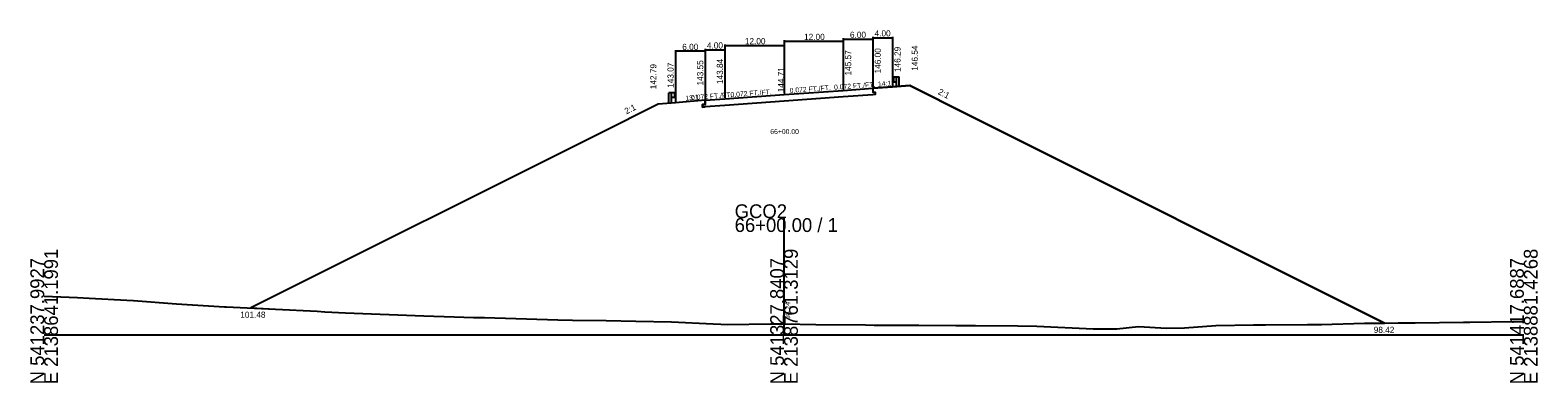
# Model space of a CAD drawing. Extents: x -14327 to 8886, y -10 to 39048.
# Drawn here: x 1997.2 to 2302.8, y 31990.3 to 32061.8 of the extents above; entities that cross this region are included whole.
import ezdxf

# ---------------------------------------------------------------- set-up
doc = ezdxf.new("R2010")
doc.units = 0
for name, color, linetype in [('Level 1', 7, 'Continuous'), ('Level 5', 7, 'Continuous'), ('Level 53', 7, 'Continuous'), ('Level 54', 7, 'Continuous'), ('Level 55', 7, 'Continuous'), ('Level 7', 7, 'Continuous'), ('RD_GPK_XS_Cell', 7, 'Continuous'), ('RD_XS_EwShp', 7, 'Continuous'), ('RD_XS_ExGround', 7, 'Continuous'), ('RD_XS_Pave', 7, 'Continuous'), ('RD_XS_TX_Elev_EX', 7, 'Continuous'), ('RD_XS_TX_Elev_PR', 7, 'Continuous'), ('RD_XS_TX_Station', 7, 'Continuous')]:
    doc.layers.add(name, color=color, linetype=linetype)

msp = doc.modelspace()

# ---------------------------------------------------------------- linework, layer by layer
at = {"layer": 'Level 1'}
for p, q in [((2172.02, 32052.11), (2172.14, 32052.2)), ((2172.02, 32052.01), (2172.14, 32051.91)), ((2172.02, 32051.58), (2172.14, 32051.67)), ((2172.02, 32051.48), (2172.14, 32051.39)), ((2172.15, 32052.2), (2172.23, 32052.22)), ((2172.15, 32051.38), (2172.23, 32051.37)), ((2172.16, 32051.87), (2172.16, 32051.72)), ((2172.23, 32052.28), (2172.23, 32051.31)), ((2172.23, 32052.28), (2172.78, 32052.28)), ((2172.23, 32051.31), (2172.78, 32051.31)), ((2172.78, 32050.29), (2172.78, 32052.28)), ((2172.78, 32052.28), (2173.34, 32052.28)), ((2173.34, 32050.29), (2173.34, 32052.28)), ((2126.66, 32047.07), (2126.66, 32049.06)), ((2127.22, 32049.06), (2126.66, 32049.06)), ((2127.22, 32047.07), (2127.22, 32049.06)), ((2127.77, 32049.06), (2127.22, 32049.06)), ((2127.77, 32048.09), (2127.22, 32048.09)), ((2127.77, 32049.06), (2127.77, 32048.09)), ((2127.85, 32048.99), (2127.77, 32049)), ((2127.85, 32048.16), (2127.77, 32048.15)), ((2127.84, 32048.65), (2127.84, 32048.5)), ((2127.98, 32048.89), (2127.86, 32048.98)), ((2127.98, 32048.79), (2127.86, 32048.7)), ((2127.98, 32048.36), (2127.86, 32048.45)), ((2127.98, 32048.26), (2127.86, 32048.17))]:
    msp.add_line(p, q, dxfattribs=at)
for centre, radius, start, end in [((2172.07, 32052.06), 0.0651, 129.0336, 230.9663), ((2172.07, 32051.53), 0.0651, 129.0336, 230.9663), ((2172.09, 32051.72), 0.0651, 302.9895, 0), ((2172.15, 32052.18), 0.026, 90, 129.0505), ((2172.09, 32051.87), 0.0651, 0, 45), ((2172.15, 32051.41), 0.026, 230.9496, 270), ((2127.91, 32048.65), 0.0651, 135, 180), ((2127.91, 32048.5), 0.0651, 180, 237.0105), ((2127.85, 32048.96), 0.026, 50.9495, 90), ((2127.85, 32048.19), 0.026, 270, 309.0504), ((2127.93, 32048.84), 0.0651, 309.0337, 50.9664), ((2127.93, 32048.31), 0.0651, 309.0337, 50.9664)]:
    msp.add_arc(centre, radius, start, end, dxfattribs=at)
at = {"layer": 'Level 5'}
for p, q in [((2162, 32048.24), (2150, 32047.37)), ((2168, 32048.67), (2162, 32048.24)), ((2168, 32050), (2168, 32049.17)), ((2168, 32049.17), (2168.5, 32049.21)), ((2168.5, 32048.71), (2168, 32048.67)), ((2168.5, 32049.21), (2168.5, 32048.71)), ((2134, 32046.72), (2133.5, 32046.69)), ((2133.5, 32046.69), (2133.5, 32046.19)), ((2133.5, 32046.19), (2134, 32046.22)), ((2134, 32047.55), (2134, 32046.72)), ((2138, 32046.51), (2134, 32046.22)), ((2150, 32047.37), (2138, 32046.51))]:
    msp.add_line(p, q, dxfattribs=at)
at = {"layer": 'Level 54'}
for p, q in [((2162, 32060.15), (2162, 32049.77)), ((2162, 32059.95), (2168, 32059.95)), ((2168, 32060.44), (2168, 32050.2)), ((2168, 32060.24), (2172, 32060.24)), ((2168, 32060.15), (2168, 32050.2)), ((2172, 32060.44), (2172, 32050.49)), ((2128, 32057.7), (2128, 32047.27)), ((2134, 32057.5), (2128, 32057.5)), ((2134, 32057.99), (2134, 32047.75)), ((2134, 32057.79), (2138, 32057.79)), ((2134, 32057.7), (2134, 32047.75)), ((2138, 32058.86), (2138, 32048.04)), ((2138, 32058.66), (2150, 32058.66)), ((2138, 32057.99), (2138, 32048.04)), ((2150, 32059.72), (2150, 32048.91)), ((2150, 32059.52), (2162, 32059.52)), ((2150, 32058.86), (2150, 32048.91)), ((2162, 32059.72), (2162, 32049.77))]:
    msp.add_line(p, q, dxfattribs=at)
at = {"layer": 'Level 7'}
for p, q in [((2168, 32050), (2172, 32050.29)), ((2172, 32050.29), (2175.5, 32050.54)), ((2175.5, 32050.54), (2187.5, 32044.54)), ((2124.5, 32046.79), (2112.5, 32040.79)), ((2128, 32047.07), (2124.5, 32046.79)), ((2134, 32047.55), (2128, 32047.07)), ((2187.5, 32044.54), (2271.74, 32002.42)), ((2112.5, 32040.79), (2041.88, 32005.48))]:
    msp.add_line(p, q, dxfattribs=at)
at = {"layer": 'RD_GPK_XS_Cell'}
for p, q in [((2150, 32000), (2150, 32023.67)), ((2000, 32000), (2150, 32000)), ((2150, 32000), (2300, 32000))]:
    msp.add_line(p, q, dxfattribs=at)
at = {"layer": 'RD_XS_EwShp'}
msp.add_lwpolyline([(2258.99, 32002.15), (2267.68, 32002.38), (2271.74, 32002.42), (2187.5, 32044.54), (2175.5, 32050.54), (2172, 32050.29), (2168, 32050), (2168, 32049.17), (2168.5, 32049.21), (2168.5, 32048.71), (2168, 32048.67), (2162, 32048.24), (2150, 32047.37), (2138, 32046.51), (2134, 32046.22), (2133.5, 32046.19), (2133.5, 32046.69), (2134, 32046.72), (2134, 32047.55), (2128, 32047.07), (2124.5, 32046.79), (2112.5, 32040.79), (2041.88, 32005.48), (2046.9, 32005.25), (2055.32, 32004.83), (2056.93, 32004.72), (2061.09, 32004.52), (2077, 32003.91), (2083.1, 32003.66), (2087.04, 32003.55), (2089.25, 32003.51), (2104.13, 32003.1), (2107.11, 32002.99), (2113.94, 32002.94), (2119.97, 32002.83), (2127.18, 32002.65), (2135.66, 32002.24), (2137.22, 32002.17), (2138.53, 32002.15), (2147.25, 32002.27), (2147.9, 32002.27), (2150, 32002.24), (2156.42, 32002.15), (2166.55, 32002.03), (2168.25, 32002.02), (2177.36, 32001.97), (2184.86, 32001.92), (2188.82, 32001.91), (2197.43, 32001.84), (2201.27, 32001.8), (2212.68, 32001.25), (2217.5, 32001.26), (2221.87, 32001.75), (2227.54, 32001.39), (2231.2, 32001.45), (2237.57, 32001.94), (2245.17, 32002.06), (2247.61, 32002.05), (2256.15, 32002.14)], close=True, dxfattribs=at)
at = {"layer": 'RD_XS_ExGround'}
for p, q in [((2000, 32007.89), (2006.76, 32007.57)), ((2006.76, 32007.57), (2009.11, 32007.44)), ((2009.11, 32007.44), (2016.79, 32007.03)), ((2016.79, 32007.03), (2018.13, 32006.97)), ((2018.13, 32006.97), (2026.83, 32006.28)), ((2026.83, 32006.28), (2036.55, 32005.73)), ((2036.55, 32005.73), (2036.91, 32005.71)), ((2036.91, 32005.71), (2046.9, 32005.25)), ((2046.9, 32005.25), (2055.32, 32004.83)), ((2055.32, 32004.83), (2056.93, 32004.72)), ((2056.93, 32004.72), (2061.09, 32004.52)), ((2061.09, 32004.52), (2077, 32003.91)), ((2077, 32003.91), (2083.1, 32003.66)), ((2083.1, 32003.66), (2087.04, 32003.55)), ((2087.04, 32003.55), (2089.25, 32003.51)), ((2089.25, 32003.51), (2104.13, 32003.1)), ((2104.13, 32003.1), (2107.11, 32002.99)), ((2107.11, 32002.99), (2113.94, 32002.94)), ((2113.94, 32002.94), (2119.97, 32002.83)), ((2119.97, 32002.83), (2127.18, 32002.65)), ((2127.18, 32002.65), (2135.66, 32002.24)), ((2135.66, 32002.24), (2137.22, 32002.17)), ((2137.22, 32002.17), (2138.53, 32002.15)), ((2138.53, 32002.15), (2147.25, 32002.27)), ((2147.25, 32002.27), (2147.9, 32002.27)), ((2147.9, 32002.27), (2150, 32002.24)), ((2150, 32002.24), (2156.42, 32002.15)), ((2156.42, 32002.15), (2166.55, 32002.03)), ((2166.55, 32002.03), (2168.25, 32002.02)), ((2168.25, 32002.02), (2177.36, 32001.97)), ((2177.36, 32001.97), (2184.86, 32001.92)), ((2184.86, 32001.92), (2188.82, 32001.91)), ((2188.82, 32001.91), (2197.43, 32001.84)), ((2197.43, 32001.84), (2201.27, 32001.8)), ((2201.27, 32001.8), (2212.68, 32001.25)), ((2231.2, 32001.45), (2237.57, 32001.94)), ((2237.57, 32001.94), (2245.17, 32002.06)), ((2245.17, 32002.06), (2247.61, 32002.05)), ((2247.61, 32002.05), (2256.15, 32002.14)), ((2256.15, 32002.14), (2258.99, 32002.15)), ((2258.99, 32002.15), (2267.68, 32002.38)), ((2267.68, 32002.38), (2274.54, 32002.45)), ((2274.54, 32002.45), (2278, 32002.48)), ((2278, 32002.48), (2287.75, 32002.57)), ((2287.75, 32002.57), (2289.04, 32002.58)), ((2289.04, 32002.58), (2297.79, 32002.74)), ((2297.79, 32002.74), (2300, 32002.75)), ((2212.68, 32001.25), (2217.5, 32001.26)), ((2217.5, 32001.26), (2221.87, 32001.75)), ((2221.87, 32001.75), (2227.54, 32001.39)), ((2227.54, 32001.39), (2231.2, 32001.45))]:
    msp.add_line(p, q, dxfattribs=at)
at = {"layer": 'RD_XS_Pave'}
for p, q in [((2134, 32047.55), (2138, 32047.84)), ((2138, 32047.84), (2150, 32048.71)), ((2150, 32048.71), (2162, 32049.57)), ((2162, 32049.57), (2168, 32050))]:
    msp.add_line(p, q, dxfattribs=at)

# ---------------------------------------------------------------- texts
at = {"layer": 'Level 53'}
for s, rotation, p in [('145.57', 90, (2163.63, 32052.57)), ('146.00', 90, (2169.63, 32053)), ('146.29', 90, (2173.63, 32053.29)), ('146.54', 90, (2177.13, 32053.54)), ('142.79', 90, (2124.13, 32049.79)), ('143.07', 90, (2127.63, 32050.07)), ('143.55', 90, (2133.63, 32050.55)), ('143.84', 90, (2137.62, 32050.84)), ('2:1', 333.4349, (2181.11, 32048.86)), ('2:1', 26.5651, (2118.05, 32044.69))]:
    msp.add_text(s, height=1.25, rotation=rotation, dxfattribs=at).set_placement(p)
for s, p in [('101.48', (2039.76, 32003.48)), ('98.42', (2269.57, 32000.42))]:
    msp.add_text(s, height=1.25, dxfattribs=at).set_placement(p)
at = {"layer": 'Level 54'}
for s, p in [('12.00', (2142.07, 32058.91)), ('12.00', (2154.07, 32059.77)), ('6.00', (2163.37, 32060.2)), ('4.00', (2168.37, 32060.49)), ('6.00', (2129.37, 32057.75)), ('4.00', (2134.37, 32058.04))]:
    msp.add_text(s, height=1.25, dxfattribs=at).set_placement(p)
at = {"layer": 'Level 55'}
for s, rotation, p in [('0.072 FT./FT.', 4.1182, (2160.18, 32049.69)), ('14:1', 4.1182, (2169.08, 32050.33)), ('13:1', 4.5739, (2130.03, 32047.49)), ('0.072 FT./FT.', 4.1182, (2131.18, 32047.6)), ('0.072 FT./FT.', 4.1182, (2139.18, 32048.18)), ('0.072 FT./FT.', 4.1182, (2151.18, 32049.04))]:
    msp.add_text(s, height=1, rotation=rotation, dxfattribs=at).set_placement(p)
at = {"layer": 'RD_GPK_XS_Cell'}
for s, p in [('GCO2', (2140, 32023.67)), ('66+00.00 / 1', (2140, 32020.87))]:
    msp.add_text(s, height=2.8, dxfattribs=at).set_placement(p)
for s, p in [('E 2138641.1991', (2002.8, 31990)), ('E 2138761.3129', (2152.8, 31990)), ('E 2138881.4268', (2302.8, 31990)), ('N 541237.9927', (2000, 31990)), ('N 541327.8407', (2150, 31990)), ('N 541417.6887', (2300, 31990))]:
    msp.add_text(s, height=2.8, rotation=90, dxfattribs=at).set_placement(p)
at = {"layer": 'RD_XS_TX_Elev_EX'}
msp.add_text('98.24', height=1, rotation=90, dxfattribs=at).set_placement((2151.25, 32003.24))
at = {"layer": 'RD_XS_TX_Elev_PR'}
msp.add_text(' 144.71', height=1.25, rotation=90, dxfattribs=at).set_placement((2150, 32048.71))
at = {"layer": 'RD_XS_TX_Station'}
msp.add_text('66+00.00', height=1, dxfattribs=at).set_placement((2147.22, 32040.71))

doc.saveas('drawing.dxf')
